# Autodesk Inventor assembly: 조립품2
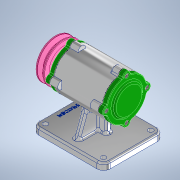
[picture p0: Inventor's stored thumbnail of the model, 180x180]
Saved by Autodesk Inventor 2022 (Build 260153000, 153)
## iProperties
Created: 2023-05
Part Number: 조립품2
Document SubType Name: Assembly
Designer: Admin
Author: Admin
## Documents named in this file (12)
- C:\Users\Admin\Desktop\730508V1008\조립품2.iam
- C:\Users\Admin\Desktop\730508V1008\부품3.ipt
- C:\Users\Admin\Desktop\730508V1008\개스킷.ipt
- C:\Users\Admin\Desktop\730508V1008\뒤커버.ipt
- C:\Users\Admin\Desktop\730508V1008\앞커버.ipt
- C:\Users\Admin\Desktop\730508V1008\베어링 6204.ipt
- C:\Users\Admin\Desktop\730508V1008\오일 실.ipt
- C:\Users\Admin\Desktop\730508V1008\축.ipt
- C:\Users\Admin\Desktop\730508V1008\볼트 M4 x 12.ipt
- C:\Users\Admin\Desktop\730508V1008\키 4 x 4.ipt
- C:\Users\Admin\Desktop\730508V1008\V-벨트풀리.ipt
- C:\Users\Admin\Desktop\730508V1008\너트 M12 x 1.25.ipt
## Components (8 placed, 6 different names)
1. 개스킷:1
2. 개스킷:2
3. KS B 2023 6204 - 20 x 47 x 14:1
4. KS B 2023 6204 - 20 x 47 x 14:2
5. KS B 2804 D D - 20 32 8:1
6. KS B 1311 (I) 4 x 4 x 12:1
7. V-벨트풀리:1
8. KS B 1012 클래스 1 일반 - 미터 M12x1.25:2
